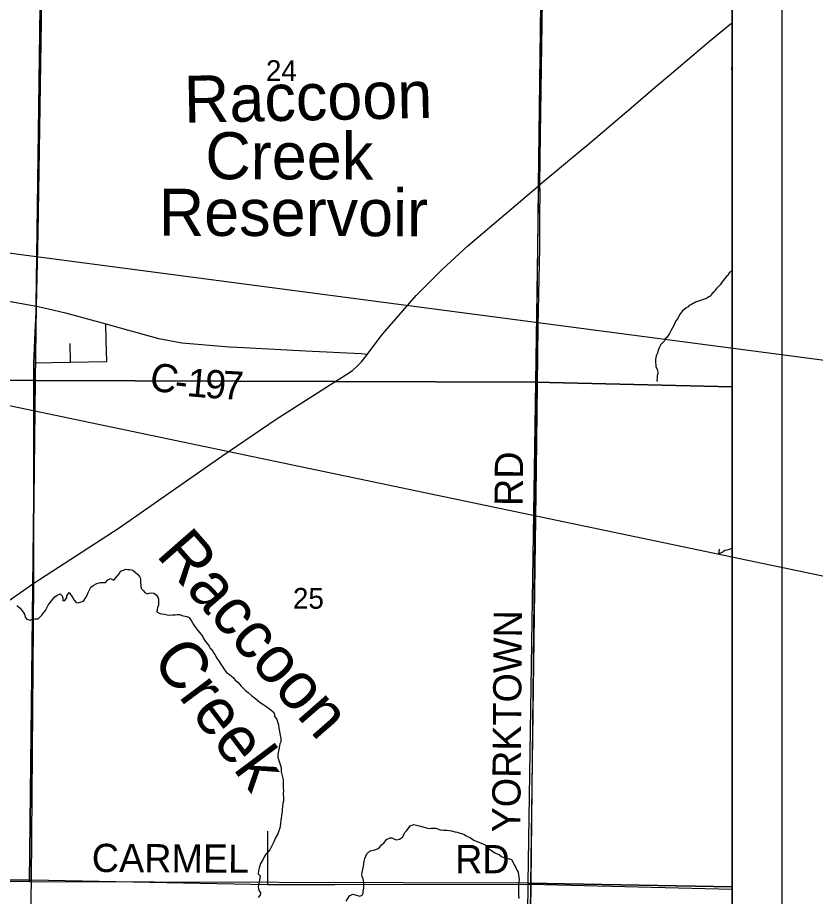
# Model space of a CAD drawing. Extents: x 0 to 34, y 0 to 22.
# Drawn here: x 7.462 to 9.068, y 15.401 to 17.171 of the extents above; entities that cross this region are included whole.
import ezdxf

# ---------------------------------------------------------------- set-up
doc = ezdxf.new("R2010")
doc.units = 0
for name, color, linetype in [('Default', 7, 'Continuous'), ('GM_X_City_Street', 7, 'Continuous'), ('GM_X_County_Road', 7, 'Continuous'), ('GM_X_County_Road_Text', 7, 'Continuous'), ('GM_X_Minor_Lake_Text', 7, 'Continuous'), ('GM_X_Minor_River', 7, 'Continuous'), ('GM_X_Minor_River_Text', 7, 'Continuous'), ('GM_X_Section', 7, 'Continuous'), ('GM_X_Section_Text', 7, 'Continuous'), ('GM_X_State_Route', 7, 'Continuous'), ('GM_X_Township', 7, 'Continuous'), ('GM_X_Township_Road', 7, 'Continuous'), ('GM_X_Township_Road_Text', 7, 'Continuous'), ('SH_Cut_Line', 7, 'Continuous'), ('SH_Data', 7, 'Continuous')]:
    doc.layers.add(name, color=color, linetype=linetype)

msp = doc.modelspace()

# ---------------------------------------------------------------- linework, layer by layer
at = {"layer": 'Default'}
for points in [[(8.9, 16.4273), (8.9, 17.4232), (8.5188, 17.4323), (8.5041, 16.4364)], [(8.9, 15.4202), (8.9, 16.4273), (8.5041, 16.4364), (8.489, 15.4271)], [(8.9, 14.4202), (8.9, 15.4202), (8.489, 15.4271), (8.4778, 14.4266)]]:
    msp.add_lwpolyline(points, close=True, dxfattribs=at)
at = {"layer": 'GM_X_City_Street'}
msp.add_line((7.568, 16.4769), (7.5674, 16.5145), dxfattribs=at)
for points in [[(7.6413, 16.4783), (7.6402, 16.5213), (7.6392, 16.5538)], [(7.4945, 16.4754), (7.568, 16.4769), (7.6413, 16.4783)]]:
    msp.add_lwpolyline(points, dxfattribs=at)
at = {"layer": 'GM_X_County_Road'}
for p, q in [((8.893, 17.1549), (8.9, 17.1605)), ((8.513, 16.8344), (8.6045, 16.9109)), ((8.1658, 16.4928), (8.1898, 16.5247)), ((7.9033, 16.5069), (8.0041, 16.5018))]:
    msp.add_line(p, q, dxfattribs=at)
for points in [[(8.7786, 17.059), (8.8056, 17.0818), (8.8543, 17.1231), (8.8923, 17.1543), (8.893, 17.1549)], [(8.6045, 16.9109), (8.6068, 16.9128), (8.706, 16.9975), (8.7413, 17.0276), (8.7709, 17.0525)], [(8.7709, 17.0525), (8.7732, 17.0544), (8.7786, 17.059)], [(8.1898, 16.5247), (8.197, 16.5342), (8.2637, 16.6108), (8.3161, 16.6632), (8.368, 16.711), (8.5096, 16.8315), (8.513, 16.8344)], [(7.2021, 16.6418), (7.2051, 16.6413), (7.3908, 16.6094), (7.4995, 16.5896)], [(7.4995, 16.5896), (7.524, 16.5845), (7.5583, 16.576), (7.6392, 16.5538), (7.6848, 16.5412)], [(7.6848, 16.5412), (7.6993, 16.5371), (7.7454, 16.5247), (7.7534, 16.5232)], [(7.7534, 16.5232), (7.7925, 16.5155), (7.8882, 16.5077), (7.9033, 16.5069)], [(8.0041, 16.5018), (8.0414, 16.4998), (8.1532, 16.4944), (8.1658, 16.4928)], [(7.4946, 16.032), (7.6661, 16.1434), (7.873, 16.2876), (7.9821, 16.362), (8.0971, 16.435), (8.1226, 16.451), (8.1356, 16.4599), (8.1462, 16.4693), (8.1537, 16.4774), (8.1658, 16.4928)], [(7.237, 15.8497), (7.2995, 15.8959), (7.4946, 16.032)]]:
    msp.add_lwpolyline(points, dxfattribs=at)
at = {"layer": 'GM_X_Minor_River'}
for points in [[(8.9, 17.0766), (8.8993, 17.0729), (8.8989, 17.0676), (8.8993, 17.0623), (8.8994, 17.057), (8.8998, 17.0539), (8.9, 17.0532)], [(8.9, 16.662), (8.8979, 16.6592), (8.8942, 16.6566), (8.8919, 16.6524), (8.8881, 16.6489), (8.8847, 16.6447), (8.8821, 16.6413), (8.8787, 16.6367), (8.8757, 16.6325), (8.8727, 16.6295), (8.8685, 16.6249), (8.8651, 16.6215), (8.8636, 16.6188), (8.8598, 16.6154), (8.8557, 16.6097), (8.853, 16.6085), (8.847, 16.6047), (8.8436, 16.6035), (8.8386, 16.6016), (8.8322, 16.6), (8.8265, 16.5974), (8.8182, 16.5931), (8.8133, 16.5912), (8.8118, 16.5885), (8.8068, 16.5855), (8.8008, 16.5809), (8.7981, 16.5778), (8.794, 16.5725), (8.7906, 16.5649), (8.7868, 16.5599), (8.785, 16.5554), (8.7835, 16.5523), (8.7801, 16.5459), (8.7771, 16.5413), (8.7752, 16.5371), (8.7737, 16.5344), (8.7714, 16.5306), (8.7692, 16.5272), (8.7654, 16.5237), (8.7639, 16.5196), (8.7594, 16.5154), (8.7567, 16.5123), (8.7548, 16.5085), (8.753, 16.5055), (8.7515, 16.5024), (8.7492, 16.4937), (8.747, 16.4895), (8.7466, 16.4864), (8.7455, 16.4819), (8.7455, 16.4758), (8.7463, 16.4712), (8.7467, 16.4678), (8.749, 16.4618), (8.7502, 16.4568), (8.7502, 16.4542)], [(8.7502, 16.4542), (8.7494, 16.4492), (8.7491, 16.445), (8.7487, 16.4412), (8.7491, 16.4378)], [(8.9, 16.1016), (8.9, 16.1016), (8.8943, 16.0997), (8.8894, 16.0981), (8.8856, 16.0977), (8.8818, 16.0947), (8.878, 16.0928), (8.8731, 16.0908), (8.8749, 16.1003)], [(7.5526, 15.9964), (7.5568, 15.9968), (7.5605, 16.0025), (7.5609, 16.0063), (7.5654, 16.0132), (7.5727, 16.0022), (7.5754, 15.9976), (7.5796, 15.9927), (7.5834, 15.992), (7.5875, 15.9935), (7.594, 15.9954), (7.5993, 16.0027), (7.6015, 16.0076), (7.6038, 16.013), (7.6064, 16.0183), (7.609, 16.0233), (7.6139, 16.0271), (7.6208, 16.0313), (7.6287, 16.0328), (7.6348, 16.0333), (7.6386, 16.0329), (7.6431, 16.0382), (7.6488, 16.0413), (7.6553, 16.0379), (7.6628, 16.0467), (7.6666, 16.0513), (7.6688, 16.0558), (7.6745, 16.0581), (7.6791, 16.0597), (7.6836, 16.0589), (7.6878, 16.059), (7.6939, 16.0578), (7.6981, 16.0541), (7.703, 16.0495), (7.7068, 16.045), (7.7088, 16.0408), (7.7092, 16.0332), (7.7104, 16.0207), (7.7142, 16.0169), (7.7176, 16.0131), (7.7226, 16.0105), (7.7264, 16.0117), (7.7321, 16.0121), (7.7359, 16.0117), (7.7408, 16.0083), (7.7439, 16.0034), (7.7454, 15.9992), (7.7455, 15.9916), (7.7451, 15.9874), (7.7432, 15.9825), (7.7429, 15.9787), (7.7421, 15.9741), (7.7478, 15.9704), (7.7516, 15.97), (7.7573, 15.9693), (7.7627, 15.9681), (7.7676, 15.9674), (7.7737, 15.9678), (7.779, 15.9682), (7.7828, 15.9686), (7.7881, 15.9686), (7.7919, 15.9664), (7.7957, 15.9656), (7.8025, 15.9642), (7.8071, 15.9623), (7.8098, 15.9585), (7.8132, 15.9528), (7.8159, 15.9486), (7.8182, 15.9445), (7.822, 15.9399), (7.8281, 15.9324), (7.8335, 15.9252), (7.8354, 15.9214), (7.8392, 15.9149), (7.8442, 15.9093), (7.8472, 15.9047), (7.8495, 15.9009), (7.853, 15.8972), (7.856, 15.8915), (7.8595, 15.8873), (7.8622, 15.8812), (7.8675, 15.8741), (7.8717, 15.8669), (7.8748, 15.8623), (7.8782, 15.8574), (7.8821, 15.8517), (7.8874, 15.8483), (7.892, 15.8445), (7.8958, 15.8415), (7.8996, 15.8362), (7.9049, 15.8321), (7.9084, 15.8283), (7.9114, 15.8241), (7.9202, 15.8154), (7.9255, 15.8113), (7.9328, 15.8056), (7.9412, 15.7988), (7.9499, 15.7913), (7.9572, 15.7867), (7.9614, 15.7837), (7.9659, 15.7807)], [(7.46, 15.9864), (7.4665, 15.9812), (7.473, 15.9732), (7.4757, 15.9694), (7.4769, 15.9634), (7.4799, 15.9592), (7.4871, 15.9569), (7.4917, 15.9593), (7.4966, 15.9597), (7.5031, 15.9601), (7.5102, 15.9673), (7.5144, 15.9723), (7.5178, 15.9765), (7.52, 15.9807), (7.523, 15.9875), (7.5298, 15.9959), (7.5325, 15.9997), (7.5366, 16.0039), (7.5415, 16.0074), (7.5472, 16.0104), (7.551, 16.0063), (7.5526, 16.0013), (7.5526, 15.9964)], [(7.9659, 15.7807), (7.9716, 15.7762), (7.9758, 15.7728), (7.9785, 15.7678), (7.9789, 15.7637), (7.9835, 15.7572), (7.9858, 15.7504), (7.9866, 15.7466), (7.9878, 15.7394), (7.9893, 15.7295), (7.9905, 15.725), (7.9917, 15.7193), (7.9913, 15.7124), (7.9898, 15.7079), (7.9887, 15.7041), (7.9872, 15.6965), (7.9861, 15.6904), (7.9858, 15.6866), (7.9858, 15.6809), (7.9873, 15.6748), (7.9904, 15.6661), (7.9912, 15.6623), (7.992, 15.6574), (7.9924, 15.6517), (7.9943, 15.6433), (7.9959, 15.6357), (7.9963, 15.6312), (7.9963, 15.6186), (7.9968, 15.6133), (7.9964, 15.608), (7.9968, 15.5993), (7.9969, 15.5928), (7.9957, 15.5882), (7.9946, 15.581), (7.9943, 15.5772), (7.9939, 15.5719), (7.9932, 15.5643), (7.9921, 15.5578), (7.9914, 15.554), (7.991, 15.5476), (7.9892, 15.5381), (7.9877, 15.5327), (7.9854, 15.527), (7.9817, 15.5202), (7.9772, 15.5107), (7.973, 15.5011), (7.9696, 15.4947), (7.9655, 15.4897), (7.9613, 15.4859), (7.9572, 15.4794), (7.9549, 15.4733), (7.9508, 15.4668), (7.9493, 15.4623), (7.9482, 15.4581), (7.9467, 15.4531), (7.9456, 15.4459), (7.9498, 15.4421), (7.9491, 15.4376), (7.9476, 15.43), (7.9472, 15.4262), (7.9461, 15.4209), (7.9465, 15.4155), (7.9477, 15.4117), (7.9507, 15.408), (7.9496, 15.403), (7.9458, 15.3984)], [(8.1231, 15.3913), (8.1295, 15.4016), (8.1364, 15.4054), (8.1462, 15.4024), (8.1508, 15.4013), (8.155, 15.4032), (8.1572, 15.4074), (8.1572, 15.4116), (8.1583, 15.4173), (8.1587, 15.4215), (8.1583, 15.4287), (8.1571, 15.4359), (8.1555, 15.4409), (8.1548, 15.445), (8.1551, 15.4488), (8.157, 15.458), (8.1577, 15.4618), (8.1588, 15.4659), (8.1592, 15.472), (8.1603, 15.477), (8.1648, 15.4865), (8.1716, 15.4926), (8.1807, 15.4942), (8.1864, 15.4968), (8.1902, 15.4995), (8.1951, 15.5052), (8.1988, 15.5079), (8.2045, 15.5155), (8.2113, 15.5186), (8.2151, 15.5186), (8.2193, 15.5168), (8.2242, 15.5149), (8.2307, 15.516), (8.2364, 15.5203), (8.2416, 15.5298), (8.2454, 15.5336), (8.2518, 15.5427), (8.259, 15.5454), (8.27, 15.5428), (8.2822, 15.5398), (8.2902, 15.5376), (8.2944, 15.538), (8.3038, 15.538), (8.3122, 15.535), (8.319, 15.5343), (8.3259, 15.534), (8.3354, 15.5329), (8.3415, 15.531), (8.3468, 15.5299), (8.3525, 15.528), (8.3601, 15.5258), (8.3643, 15.5228), (8.3734, 15.519), (8.3803, 15.5141), (8.3913, 15.5096), (8.4027, 15.5043), (8.4115, 15.496), (8.4221, 15.4888), (8.4317, 15.4847), (8.4358, 15.4809), (8.4404, 15.4791), (8.445, 15.4768), (8.4492, 15.4768), (8.4556, 15.475), (8.4583, 15.4704), (8.4614, 15.4643), (8.4644, 15.459), (8.466, 15.4549), (8.469, 15.4496), (8.4702, 15.4443), (8.4706, 15.4401), (8.471, 15.4344), (8.4706, 15.4298), (8.4699, 15.4218), (8.47, 15.404), (8.4704, 15.3964)]]:
    msp.add_lwpolyline(points, dxfattribs=at)
at = {"layer": 'GM_X_Section'}
for points in [[(6.4919, 17.4489), (7.5107, 17.4428), (7.4967, 16.4401), (6.481, 16.4419)], [(8.5188, 17.4323), (8.5041, 16.4364), (7.4967, 16.4401), (7.5107, 17.4428)], [(6.481, 16.4419), (7.4967, 16.4401), (7.4854, 15.4301), (6.4743, 15.4308)], [(8.5041, 16.4364), (8.489, 15.4271), (7.4854, 15.4301), (7.4967, 16.4401)]]:
    msp.add_lwpolyline(points, close=True, dxfattribs=at)
at = {"layer": 'GM_X_State_Route'}
msp.add_line((7.4708, 14.5691), (7.4898, 15.4344), dxfattribs=at)
for points in [[(7.4978, 16.5516), (7.4995, 16.5896), (7.5028, 16.737), (7.5058, 16.9041), (7.5078, 17.0349), (7.5097, 17.1641), (7.51, 17.193), (7.5103, 17.221), (7.511, 17.2637), (7.5116, 17.3367), (7.5116, 17.3377)], [(7.4941, 16.445), (7.4945, 16.4754), (7.4978, 16.5516)], [(7.4898, 15.4344), (7.4946, 16.032), (7.4941, 16.445)]]:
    msp.add_lwpolyline(points, dxfattribs=at)
at = {"layer": 'GM_X_Township'}
msp.add_lwpolyline([(4.5784, 20.3968), (5.284, 20.4086), (5.325, 20.4092), (6.5316, 20.4254), (6.5575, 20.4259), (7.5409, 20.4415), (8.556, 20.4544), (8.5437, 19.4556), (8.5436, 19.4447), (8.5388, 18.7451), (8.5216, 17.7888), (8.5215, 17.7806), (8.5214, 17.7731), (8.5094, 16.832), (8.5093, 16.83), (8.4947, 15.4259), (8.4895, 15.0042)], dxfattribs=at)
at = {"layer": 'GM_X_Township_Road'}
for p, q in [((8.513, 16.8344), (8.5144, 16.9349)), ((7.9654, 15.4247), (7.9652, 15.5321)), ((6.7245, 15.4335), (7.4898, 15.4344)), ((8.0999, 15.4249), (8.495, 15.4254)), ((8.495, 15.4254), (8.9, 15.4152))]:
    msp.add_line(p, q, dxfattribs=at)
msp.add_lwpolyline([(8.9, 14.4215), (8.9, 20.4518), (8.556, 20.4544), (8.5437, 19.4556), (8.5436, 19.4447), (8.5388, 18.7451), (8.5216, 17.7888), (8.5215, 17.7806), (8.5214, 17.7731), (8.5094, 16.832), (8.5093, 16.83), (8.4947, 15.4259), (8.4895, 15.0042), (8.4811, 14.4273), (8.4833, 14.4273), (8.6169, 14.4256), (8.6362, 14.4253), (8.7095, 14.4242), (8.7648, 14.4233), (8.8009, 14.4228), (8.8456, 14.4221)], close=True, dxfattribs=at)
for points in [[(8.5144, 16.9349), (8.5176, 17.1591), (8.5215, 17.4432), (8.5206, 17.5327), (8.52, 17.613), (8.5214, 17.6486), (8.5247, 17.7191), (8.5255, 17.759), (8.5262, 17.7785)], [(8.508, 16.4317), (8.5093, 16.5495), (8.5126, 16.7069), (8.5131, 16.7718), (8.5139, 16.8185), (8.513, 16.8344)], [(8.495, 15.4254), (8.5061, 16.2616), (8.508, 16.4317)], [(7.4898, 15.4344), (7.9654, 15.4247), (8.0999, 15.4249)], [(8.4813, 14.4267), (8.4898, 15.0036), (8.495, 15.4254)]]:
    msp.add_lwpolyline(points, dxfattribs=at)
at = {"layer": 'SH_Cut_Line'}
msp.add_lwpolyline([(8.9, 14.4215), (8.9, 20.9), (2.1, 20.9)], dxfattribs=at)
at = {"layer": 'SH_Data'}
for p, q in [((9, 21), (9, 14)), ((8.9, 20.9), (8.9, 14.1))]:
    msp.add_line(p, q, dxfattribs=at)
msp.add_lwpolyline([(3.5095, 17.2146), (9.8001, 15.8963), (9.8001, 16.3863)], close=True, dxfattribs=at)

# ---------------------------------------------------------------- texts
at = {"layer": 'GM_X_County_Road_Text'}
for s, rotation, p in [('C', 346.5317, (7.7236, 16.4238)), ('1', 354.5927, (7.8008, 16.4087)), ('9', 356.365, (7.8375, 16.4053)), ('7', 356.8303, (7.873, 16.403)), ('-', 353.0323, (7.7759, 16.4117))]:
    msp.add_text(s, height=0.0568, rotation=rotation, dxfattribs=at).set_placement(p)
at = {"layer": 'GM_X_Minor_Lake_Text'}
for s, rotation, p in [('Raccoon', 1.178, (7.7973, 16.9588)), ('Creek', 359.8958, (7.8395, 16.8453)), ('Reservoir', 359.896, (7.7456, 16.7314))]:
    msp.add_text(s, height=0.09475, rotation=rotation, dxfattribs=at).set_placement(p)
at = {"layer": 'GM_X_Minor_River_Text'}
for s, rotation, p in [('Raccoon', 311.1758, (7.7387, 16.0878)), ('Creek', 306.8935, (7.7295, 15.8767))]:
    msp.add_text(s, height=0.09475, rotation=rotation, dxfattribs=at).set_placement(p)
at = {"layer": 'GM_X_Section_Text'}
for s, p in [('24', (7.9615, 17.0432)), ('25', (8.0159, 15.9802))]:
    msp.add_text(s, height=0.04186, rotation=0, dxfattribs=at).set_placement(p)
at = {"layer": 'GM_X_Township_Road_Text'}
for s, rotation, p in [('RD', 89.5045, (8.4784, 16.1869)), ('YORKTOWN', 89.5287, (8.4734, 15.5294)), ('CARMEL', 359.6789, (7.6108, 15.45)), ('RD', 0, (8.3424, 15.4474))]:
    msp.add_text(s, height=0.05682, rotation=rotation, dxfattribs=at).set_placement(p)

doc.saveas('drawing.dxf')
